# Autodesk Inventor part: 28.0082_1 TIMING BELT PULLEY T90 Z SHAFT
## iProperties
Created: 2007-06
Part Number: 28.0082_1 TIMING BELT PULLEY T90 Z SHAFT
Document SubType Name: Modeling
Designer: Andy Moles
Material: Steel
Density: 7.85 g/cm^3
Author: Andy Moles
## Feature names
1. Extrusion1
2. Extrusion2
3. Hole1
4. Chamfer1
5. Extrusion3
